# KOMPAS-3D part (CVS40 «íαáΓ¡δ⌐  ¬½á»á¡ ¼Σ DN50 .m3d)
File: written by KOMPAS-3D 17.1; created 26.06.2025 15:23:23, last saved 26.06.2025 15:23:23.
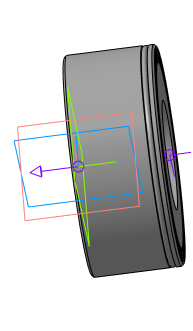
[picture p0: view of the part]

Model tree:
1. Эскиз:1
2. Элемент вращения:1
     Угол 1 = 360
3. Присоединительная точка:1
4. Присоединительная точка:2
